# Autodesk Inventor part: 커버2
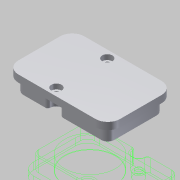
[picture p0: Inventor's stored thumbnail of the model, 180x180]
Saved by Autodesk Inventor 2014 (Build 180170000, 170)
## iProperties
Company: 한국ATC센터
Created: 2015-04
Part Number: 커버2
Document SubType Name: Modeling
Designer: KYOUNG IL JANG
Density: 2.71 g/cm^3
Material: 알루미늄 6061
Mass: 222.992 g
Surface Area: 213.51 cm^2
Volume: 82.2849 cm^3
Appearance: 매끄러움 - 흰색
Author: KYOUNG IL JANG
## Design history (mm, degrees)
node "작업 평면1"
sketch "스케치1"
  geometry: L1 (-16.986, 27.5)-(-38, 27.5) reference; L2 (-45, 20.5)-(-45, -20.5) reference; L3 (-38, -27.5)-(-16.986, -27.5) reference; L4 (0.986, -27.5)-(38, -27.5) reference; L5 (45, -20.5)-(45, 20.5) reference; L6 (38, 27.5)-(0.986, 27.5) reference; C1 r 25 at (15, 0); A1 r 3 centre (-16.986, 24.5) between (-13.991, 24.667) and (-16.986, 27.5) reference; A2 r 7 centre (-38, 20.5) between (-38, 27.5) and (-45, 20.5) reference; A3 r 7 centre (-38, -20.5) between (-45, -20.5) and (-38, -27.5) reference; A4 r 3 centre (-16.986, -24.5) between (-16.986, -27.5) and (-13.991, -24.667) reference; A5 r 6 centre (-8, -25) between (-2.009, -24.667) and (-13.991, -24.667) reference; A6 r 3 centre (0.986, -24.5) between (-2.009, -24.667) and (0.986, -27.5) reference; A7 r 7 centre (38, -20.5) between (38, -27.5) and (45, -20.5) reference; A8 r 7 centre (38, 20.5) between (45, 20.5) and (38, 27.5) reference; A9 r 3 centre (0.986, 24.5) between (0.986, 27.5) and (-2.009, 24.667) reference; A10 r 6 centre (-8, 25) between (-13.991, 24.667) and (-2.009, 24.667) reference; 1 further point
  constraints: 20 point on circle, 12 end point, 11 centre point, 4 horizontal, 2 vertical, 36 other
extrude "돌출1" new body sketch "스케치1" distance "d0" = 14; taper "d1" = 0 deg
sketch "스케치2"
  geometry: L1 (38, -32.5)-(-38, -32.5) reference; L2 (50, 20.5)-(50, -20.5) reference; L3 (-38, 32.5)-(38, 32.5) reference; L4 (-50, -20.5)-(-50, 20.5) reference; A1 r 12 centre (38, -20.5) between (38, -32.5) and (50, -20.5) reference; A2 r 12 centre (38, 20.5) between (50, 20.5) and (38, 32.5) reference; A3 r 12 centre (-38, 20.5) between (-38, 32.5) and (-50, 20.5) reference; A4 r 12 centre (-38, -20.5) between (-50, -20.5) and (-38, -32.5) reference; 1 further point
extrude "돌출2" join sketch "스케치2" distance "d2" = 7; taper "d3" = 0 deg
sketch "스케치3"
  geometry: C1 r 2.458 at (-8, 25) reference; C2 r 2.458 at (-8, -25) reference; 1 further point
hole "구멍1" sketch "스케치3" at (-8, -25), (-8, 25) diameter "d4" = 6; stored, may be unused: countersink angle "d8" = 90 deg, drill point angle "d10" = 118 deg; dims "d5" = 6, "d6" = 10, "d7" = 5, "d9" = 8
fillet "모깎기1" dims "d11" = 0.3
chamfer "모따기1" distance "d12" = 1; stored, may be unused: second distance "d13" = 2, angle "d14" = 45 deg
node "솔리드1"
node "참조2"
node "참조3"
node "참조4"
node "참조5"
node "참조6"
node "참조7"
node "참조8"
node "참조9"
node "참조10"
node "참조11"
